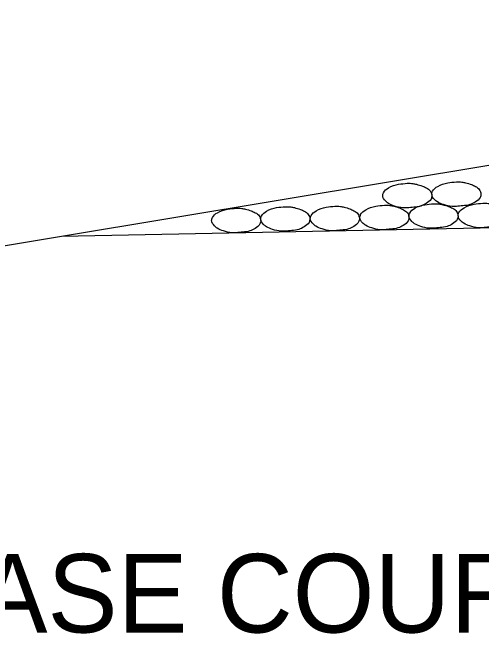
# Model space of a CAD drawing. Extents: x 60325 to 61047, y 53669 to 53767.
# Drawn here: x 60517.691 to 60520.67, y 53730.656 to 53734.751 of the extents above; entities that cross this region are included whole.
import ezdxf

# ---------------------------------------------------------------- set-up
doc = ezdxf.new("R2010")
doc.units = 0
doc.layers.add('R_Border Prem', color=7, linetype='Continuous')

msp = doc.modelspace()

# ---------------------------------------------------------------- linework, layer by layer
at = {"layer": 'R_Border Prem'}
for p, q in [((60526.5451, 53734.7512), (60517.9991, 53733.3269)), ((60571.5451, 53734.3978), (60517.9991, 53733.3269)), ((60517.9991, 53733.3269), (60506.5451, 53731.4179))]:
    msp.add_line(p, q, dxfattribs=at)
for points in [[(60520.1998, 53733.6661), (60520.1448, 53733.6598), (60520.081, 53733.6373), (60520.0485, 53733.6061), (60520.0435, 53733.5873), (60520.061, 53733.5536), (60520.0798, 53733.5386), (60520.1185, 53733.5211), (60520.1723, 53733.5098), (60520.1998, 53733.5098), (60520.241, 53733.5136), (60520.286, 53733.5211), (60520.3198, 53733.5373), (60520.351, 53733.5661), (60520.356, 53733.5873), (60520.346, 53733.6173), (60520.321, 53733.6373), (60520.296, 53733.6486), (60520.2585, 53733.6598), (60520.2348, 53733.6648), (60520.1998, 53733.6661)], [(60520.5121, 53733.6755), (60520.4571, 53733.6693), (60520.3934, 53733.6468), (60520.3609, 53733.6155), (60520.3559, 53733.5968), (60520.3734, 53733.563), (60520.3921, 53733.548), (60520.4309, 53733.5305), (60520.4846, 53733.5193), (60520.5121, 53733.5193), (60520.5534, 53733.523), (60520.5984, 53733.5305), (60520.6321, 53733.5468), (60520.6634, 53733.5755), (60520.6684, 53733.5968), (60520.6584, 53733.6268), (60520.6334, 53733.6468), (60520.6084, 53733.658), (60520.5709, 53733.6693), (60520.5471, 53733.6743), (60520.5121, 53733.6755)], [(60520.3669, 53733.5363), (60520.3119, 53733.53), (60520.2482, 53733.5075), (60520.2157, 53733.4763), (60520.2107, 53733.4575), (60520.2282, 53733.4238), (60520.2469, 53733.4088), (60520.2857, 53733.3913), (60520.3394, 53733.38), (60520.3669, 53733.38), (60520.4082, 53733.3838), (60520.4532, 53733.3913), (60520.4869, 53733.4075), (60520.5182, 53733.4363), (60520.5232, 53733.4575), (60520.5132, 53733.4875), (60520.4882, 53733.5075), (60520.4632, 53733.5188), (60520.4257, 53733.53), (60520.4019, 53733.535), (60520.3669, 53733.5363)], [(60520.6797, 53733.5395), (60520.6247, 53733.5333), (60520.5609, 53733.5108), (60520.5284, 53733.4795), (60520.5234, 53733.4608), (60520.5409, 53733.427), (60520.5597, 53733.412), (60520.5984, 53733.3945), (60520.6522, 53733.3833), (60520.6797, 53733.3833), (60520.7209, 53733.387), (60520.7659, 53733.3945), (60520.7997, 53733.4108), (60520.8309, 53733.4395), (60520.8359, 53733.4608), (60520.8259, 53733.4908), (60520.8009, 53733.5108), (60520.7759, 53733.522), (60520.7384, 53733.5333), (60520.7147, 53733.5383), (60520.6797, 53733.5395)], [(60519.1113, 53733.5079), (60519.0563, 53733.5016), (60518.9926, 53733.4791), (60518.9601, 53733.4479), (60518.9551, 53733.4291), (60518.9726, 53733.3954), (60518.9913, 53733.3804), (60519.0301, 53733.3629), (60519.0838, 53733.3516), (60519.1113, 53733.3516), (60519.1526, 53733.3554), (60519.1976, 53733.3629), (60519.2313, 53733.3791), (60519.2626, 53733.4079), (60519.2676, 53733.4291), (60519.2576, 53733.4591), (60519.2326, 53733.4791), (60519.2076, 53733.4904), (60519.1701, 53733.5016), (60519.1463, 53733.5066), (60519.1113, 53733.5079)], [(60519.4237, 53733.5173), (60519.3687, 53733.5111), (60519.3049, 53733.4886), (60519.2724, 53733.4573), (60519.2674, 53733.4386), (60519.2849, 53733.4048), (60519.3037, 53733.3898), (60519.3424, 53733.3723), (60519.3962, 53733.3611), (60519.4237, 53733.3611), (60519.4649, 53733.3648), (60519.5099, 53733.3723), (60519.5437, 53733.3886), (60519.5749, 53733.4173), (60519.5799, 53733.4386), (60519.5699, 53733.4686), (60519.5449, 53733.4886), (60519.5199, 53733.4998), (60519.4824, 53733.5111), (60519.4587, 53733.5161), (60519.4237, 53733.5173)], [(60519.7391, 53733.5205), (60519.6841, 53733.5142), (60519.6204, 53733.4917), (60519.5879, 53733.4605), (60519.5829, 53733.4417), (60519.6004, 53733.408), (60519.6191, 53733.393), (60519.6579, 53733.3755), (60519.7116, 53733.3642), (60519.7391, 53733.3642), (60519.7804, 53733.368), (60519.8254, 53733.3755), (60519.8591, 53733.3917), (60519.8904, 53733.4205), (60519.8954, 53733.4417), (60519.8854, 53733.4717), (60519.8604, 53733.4917), (60519.8354, 53733.503), (60519.7979, 53733.5142), (60519.7741, 53733.5192), (60519.7391, 53733.5205)], [(60520.0546, 53733.5268), (60519.9996, 53733.5206), (60519.9359, 53733.4981), (60519.9034, 53733.4668), (60519.8984, 53733.4481), (60519.9159, 53733.4143), (60519.9346, 53733.3993), (60519.9734, 53733.3818), (60520.0271, 53733.3706), (60520.0546, 53733.3706), (60520.0959, 53733.3743), (60520.1409, 53733.3818), (60520.1746, 53733.3981), (60520.2059, 53733.4268), (60520.2109, 53733.4481), (60520.2009, 53733.4781), (60520.1759, 53733.4981), (60520.1509, 53733.5093), (60520.1134, 53733.5206), (60520.0896, 53733.5256), (60520.0546, 53733.5268)]]:
    msp.add_spline(points, degree=3, dxfattribs=at)

# ---------------------------------------------------------------- texts
msp.add_text('AGGREGATE BASE COURSE (CL. 7)', height=0.5, dxfattribs=at).set_placement((60512.5976, 53730.8064))

doc.saveas('drawing.dxf')
